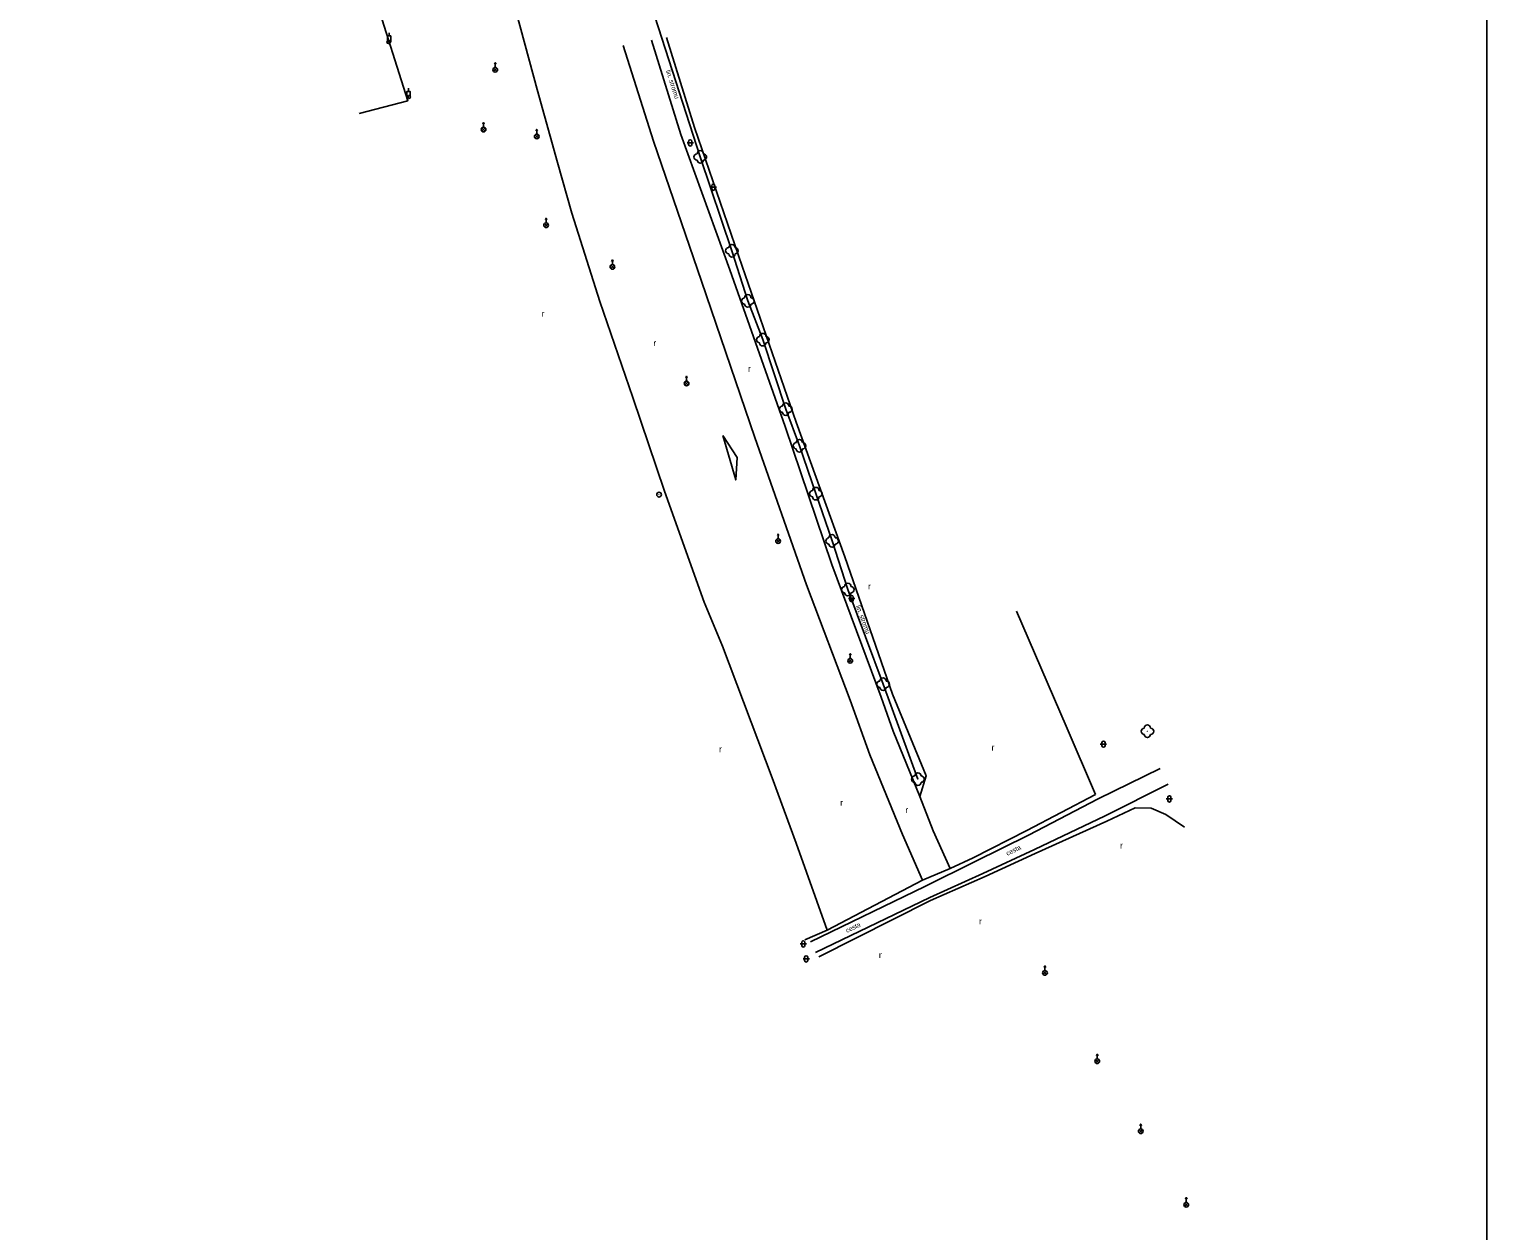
# Model space of a CAD drawing. Extents: x -582188 to -561562, y -1187250 to -1183500.
# Drawn here: x -575231.7 to -575000, y -1184245.2 to -1184054.2 of the extents above; entities that cross this region are included whole.
import ezdxf

# ---------------------------------------------------------------- set-up
doc = ezdxf.new("R2010")
doc.units = 0
for name, color, linetype in [('MAP_ZN_BP', 7, 'Continuous'), ('POMOC_POPIS', 7, 'Continuous'), ('ROZHRANÍ_PLOCH', 7, 'Continuous'), ('RÁMY_ML', 7, 'Continuous'), ('ZELEŇ', 7, 'Continuous'), ('ZN_BP', 7, 'Continuous'), ('ZN_DOPLŇKOVÉ', 7, 'Continuous'), ('ZN_KULTUR', 7, 'Continuous')]:
    doc.layers.add(name, color=color, linetype=linetype)

msp = doc.modelspace()

# ---------------------------------------------------------------- linework, layer by layer
at = {"layer": 'MAP_ZN_BP'}
for radius in [0.375, 0.0005]:
    msp.add_circle((-575131.55, -1184128.201), radius, dxfattribs=at)
at = {"layer": 'ROZHRANÍ_PLOCH'}
for points in [[(-575081.29, -1184186.5), (-575072.84, -1184182.35), (-575061.75, -1184176.54), (-575051.91, -1184171.73)], [(-575071.91, -1184184.6), (-575060.65, -1184179.26), (-575050.64, -1184174.21)], [(-575081.29, -1184186.5), (-575089.3, -1184190.46), (-575107.48, -1184199.28)], [(-575071.91, -1184184.6), (-575080.09, -1184188.4), (-575088.51, -1184192.26), (-575106.68, -1184200.98)]]:
    msp.add_lwpolyline(points, dxfattribs=at)
at = {"layer": 'RÁMY_ML'}
msp.add_lwpolyline([(-575312.5, -1184250), (-575000, -1184250), (-575000, -1184000)], dxfattribs=at)
at = {"layer": 'ZELEŇ'}
msp.add_line((-575073.09, -1184181.61), (-575062.19, -1184175.86), dxfattribs=at)
for points in [[(-575179.21, -1184067.59), (-575171.49, -1184065.59), (-575176.62, -1184049.33), (-575179.23, -1184040.68), (-575185.64, -1184019.24), (-575189.1, -1184003.71), (-575190.37, -1183993.69), (-575191.86, -1183981.98), (-575193.32, -1183970.15), (-575194.4, -1183962.03), (-575192.31, -1183959.76)], [(-575104.83, -1184197.43), (-575109.77, -1184183.61), (-575113.58, -1184173.2), (-575121.49, -1184152.31), (-575124.38, -1184145.28), (-575130.7, -1184127.65), (-575135.73, -1184112.74), (-575140.94, -1184097.5), (-575145.39, -1184083.44), (-575147.68, -1184075.42), (-575150.9, -1184063.82), (-575153.51, -1184054.2), (-575156.03, -1184045), (-575158.66, -1184034.48), (-575160.37, -1184027)], [(-575090.41, -1184173.42), (-575095.95, -1184158.33), (-575101.56, -1184143.29), (-575104.06, -1184135.55), (-575106.64, -1184128.04), (-575109.25, -1184120.43), (-575111.42, -1184114.61), (-575115.07, -1184103.56), (-575117.45, -1184097.41), (-575119.97, -1184089.43), (-575125, -1184074.52), (-575132.23, -1184052.22)], [(-575089.69, -1184189.5), (-575092.87, -1184182.2), (-575098.08, -1184169.56), (-575101.17, -1184160.88), (-575108.1, -1184142.54), (-575116.35, -1184119.12), (-575124.82, -1184094.24), (-575132.43, -1184072.01), (-575137.25, -1184056.81)], [(-575085.28, -1184187.62), (-575087.97, -1184181.62), (-575090.13, -1184176.19), (-575094.34, -1184165.77), (-575096.23, -1184160.37), (-575104.08, -1184139.29), (-575111.53, -1184117.36), (-575120.29, -1184092.46), (-575128.08, -1184070.93), (-575132.73, -1184055.97)], [(-575090.13, -1184176.19), (-575089.13, -1184172.9), (-575094.46, -1184159.89), (-575102.02, -1184138.09), (-575109.77, -1184116.67), (-575118.35, -1184091.9), (-575125.92, -1184069.83), (-575130.39, -1184055.53)], [(-575121.44, -1184118.78), (-575119.14, -1184122.27), (-575119.36, -1184125.86), (-575121.44, -1184118.78)], [(-575062.19, -1184175.86), (-575066.83, -1184165), (-575074.74, -1184146.72)], [(-575079.73, -1184188.92), (-575071.8, -1184185.22), (-575060.37, -1184180.12), (-575055.89, -1184177.97), (-575053.34, -1184178.03), (-575051, -1184179.05), (-575048.04, -1184181.08)], [(-575073.09, -1184181.61), (-575081.66, -1184185.94), (-575085.28, -1184187.62), (-575089.69, -1184189.5), (-575104.83, -1184197.43), (-575108.41, -1184198.96)], [(-575079.73, -1184188.92), (-575088.41, -1184192.7), (-575106.16, -1184201.67)]]:
    msp.add_lwpolyline(points, dxfattribs=at)
for centre in [(-575125, -1184074.52), (-575119.97, -1184089.43), (-575117.45, -1184097.41), (-575115.07, -1184103.56), (-575111.42, -1184114.61), (-575109.25, -1184120.43), (-575106.64, -1184128.04), (-575104.06, -1184135.55), (-575101.56, -1184143.29), (-575095.95, -1184158.33), (-575053.94, -1184165.81), (-575090.41, -1184173.42)]:
    msp.add_circle(centre, 0.0005, dxfattribs=at)
for centre, start, end in [((-575125.5, -1184074.52), 89.99999, 269.99999), ((-575125, -1184074.02), 0, 179.99999), ((-575125, -1184075.02), 179.99999, 359.99999), ((-575124.5, -1184074.52), 270, 89.99999), ((-575120.47, -1184089.43), 89.99999, 269.99999), ((-575119.97, -1184088.93), 0, 179.99999), ((-575119.47, -1184089.43), 270, 89.99999), ((-575119.97, -1184089.93), 179.99999, 359.99999), ((-575117.45, -1184096.91), 0, 179.99999), ((-575117.95, -1184097.41), 89.99999, 269.99999), ((-575117.45, -1184097.91), 179.99999, 359.99999), ((-575116.95, -1184097.41), 270, 89.99999), ((-575115.57, -1184103.56), 89.99999, 269.99999), ((-575115.07, -1184103.06), 0, 179.99999), ((-575114.57, -1184103.56), 270, 89.99999), ((-575115.07, -1184104.06), 179.99999, 359.99999), ((-575111.92, -1184114.61), 89.99999, 269.99999), ((-575111.42, -1184114.11), 0, 179.99999), ((-575110.92, -1184114.61), 270, 89.99999), ((-575111.42, -1184115.11), 179.99999, 359.99999), ((-575109.25, -1184119.93), 0, 179.99999), ((-575109.75, -1184120.43), 89.99999, 269.99999), ((-575109.25, -1184120.93), 179.99999, 359.99999), ((-575108.75, -1184120.43), 270, 89.99999), ((-575107.14, -1184128.04), 89.99999, 269.99999), ((-575106.64, -1184127.54), 0, 179.99999), ((-575106.64, -1184128.54), 179.99999, 359.99999), ((-575106.14, -1184128.04), 270, 89.99999), ((-575104.56, -1184135.55), 89.99999, 269.99999), ((-575104.06, -1184135.05), 0, 179.99999), ((-575103.56, -1184135.55), 270, 89.99999), ((-575104.06, -1184136.05), 179.99999, 359.99999), ((-575102.06, -1184143.29), 89.99999, 269.99999), ((-575101.56, -1184142.79), 0, 179.99999), ((-575101.06, -1184143.29), 270, 89.99999), ((-575101.56, -1184143.79), 179.99999, 359.99999), ((-575096.45, -1184158.33), 89.99999, 269.99999), ((-575095.95, -1184157.83), 0, 179.99999), ((-575095.95, -1184158.83), 179.99999, 359.99999), ((-575095.45, -1184158.33), 270, 89.99999), ((-575054.44, -1184165.81), 89.99999, 269.99999), ((-575053.94, -1184165.31), 0, 179.99999), ((-575053.44, -1184165.81), 270, 89.99999), ((-575053.94, -1184166.31), 179.99999, 359.99999), ((-575090.41, -1184172.92), 0, 179.99999), ((-575090.91, -1184173.42), 89.99999, 269.99999), ((-575090.41, -1184173.92), 179.99999, 359.99999), ((-575089.91, -1184173.42), 270, 89.99999)]:
    msp.add_arc(centre, 0.5, start, end, dxfattribs=at)
at = {"layer": 'ZN_BP'}
for p, q in [((-575157.855, -1184060.934), (-575157.326, -1184060.406)), ((-575157.326, -1184060.938), (-575157.855, -1184060.406)), ((-575157.59, -1184060.295), (-575157.59, -1184059.545)), ((-575159.715, -1184070.434), (-575159.186, -1184069.906)), ((-575159.186, -1184070.438), (-575159.715, -1184069.906)), ((-575159.45, -1184069.795), (-575159.45, -1184069.045)), ((-575150.99, -1184070.885), (-575150.99, -1184070.135)), ((-575151.255, -1184071.524), (-575150.726, -1184070.996)), ((-575150.726, -1184071.528), (-575151.255, -1184070.996)), ((-575149.5, -1184085.005), (-575149.5, -1184084.255)), ((-575149.765, -1184085.644), (-575149.236, -1184085.116)), ((-575149.236, -1184085.648), (-575149.765, -1184085.116)), ((-575139.225, -1184092.264), (-575138.696, -1184091.736)), ((-575138.696, -1184092.268), (-575139.225, -1184091.736)), ((-575138.96, -1184091.625), (-575138.96, -1184090.875)), ((-575127.455, -1184110.774), (-575126.926, -1184110.246)), ((-575126.926, -1184110.778), (-575127.455, -1184110.246)), ((-575127.19, -1184110.135), (-575127.19, -1184109.385)), ((-575112.895, -1184135.844), (-575112.366, -1184135.316)), ((-575112.366, -1184135.848), (-575112.895, -1184135.316)), ((-575112.63, -1184135.205), (-575112.63, -1184134.455)), ((-575101.435, -1184154.874), (-575100.906, -1184154.346)), ((-575100.906, -1184154.878), (-575101.435, -1184154.346)), ((-575101.17, -1184154.235), (-575101.17, -1184153.485)), ((-575070.485, -1184204.494), (-575069.956, -1184203.966)), ((-575069.956, -1184204.498), (-575070.485, -1184203.966)), ((-575070.22, -1184203.855), (-575070.22, -1184203.105)), ((-575062.185, -1184218.534), (-575061.656, -1184218.006)), ((-575061.656, -1184218.538), (-575062.185, -1184218.006)), ((-575061.92, -1184217.895), (-575061.92, -1184217.145)), ((-575055.01, -1184229.005), (-575055.01, -1184228.255)), ((-575055.275, -1184229.644), (-575054.746, -1184229.116)), ((-575054.746, -1184229.648), (-575055.275, -1184229.116)), ((-575047.77, -1184240.695), (-575047.77, -1184239.945)), ((-575048.035, -1184241.334), (-575047.506, -1184240.806)), ((-575047.506, -1184241.338), (-575048.035, -1184240.806))]:
    msp.add_line(p, q, dxfattribs=at)
for points in [[(-575157.715, -1184059.795), (-575157.59, -1184059.545), (-575157.465, -1184059.795)], [(-575159.575, -1184069.295), (-575159.45, -1184069.045), (-575159.325, -1184069.295)], [(-575151.115, -1184070.385), (-575150.99, -1184070.135), (-575150.865, -1184070.385)], [(-575149.625, -1184084.505), (-575149.5, -1184084.255), (-575149.375, -1184084.505)], [(-575139.085, -1184091.125), (-575138.96, -1184090.875), (-575138.835, -1184091.125)], [(-575127.315, -1184109.635), (-575127.19, -1184109.385), (-575127.065, -1184109.635)], [(-575112.755, -1184134.705), (-575112.63, -1184134.455), (-575112.505, -1184134.705)], [(-575101.295, -1184153.735), (-575101.17, -1184153.485), (-575101.045, -1184153.735)], [(-575070.345, -1184203.355), (-575070.22, -1184203.105), (-575070.095, -1184203.355)], [(-575062.045, -1184217.395), (-575061.92, -1184217.145), (-575061.795, -1184217.395)], [(-575055.135, -1184228.505), (-575055.01, -1184228.255), (-575054.885, -1184228.505)], [(-575047.895, -1184240.195), (-575047.77, -1184239.945), (-575047.645, -1184240.195)]]:
    msp.add_lwpolyline(points, dxfattribs=at)
for centre, radius in [((-575174.54, -1184056.25), 0.25), ((-575174.54, -1184056.25), 0.0005), ((-575157.59, -1184060.67), 0.375), ((-575171.32, -1184064.99), 0.25), ((-575171.32, -1184064.99), 0.0005), ((-575159.45, -1184070.17), 0.375), ((-575150.99, -1184071.26), 0.375), ((-575149.5, -1184085.38), 0.375), ((-575138.96, -1184092), 0.375), ((-575127.19, -1184110.51), 0.375), ((-575112.63, -1184135.58), 0.375), ((-575101.17, -1184154.61), 0.375), ((-575070.22, -1184204.23), 0.375), ((-575061.92, -1184218.27), 0.375), ((-575055.01, -1184229.38), 0.375), ((-575047.77, -1184241.07), 0.375)]:
    msp.add_circle(centre, radius, dxfattribs=at)
at = {"layer": 'ZN_DOPLŇKOVÉ'}
for p, q in [((-575174.44, -1184055.29), (-575174.44, -1184054.79)), ((-575171.36, -1184064.09), (-575171.36, -1184063.59))]:
    msp.add_line(p, q, dxfattribs=at)
for points in [[(-575174.69, -1184056.29), (-575174.69, -1184055.29), (-575174.19, -1184055.29), (-575174.19, -1184056.29)], [(-575171.61, -1184065.09), (-575171.61, -1184064.09), (-575171.11, -1184064.09), (-575171.11, -1184065.09)]]:
    msp.add_lwpolyline(points, dxfattribs=at)
at = {"layer": 'ZN_KULTUR'}
for p, q in [((-575127.1, -1184072.29), (-575126.1, -1184072.29)), ((-575126.85, -1184072.54), (-575126.85, -1184072.04)), ((-575126.35, -1184072.54), (-575126.35, -1184072.04)), ((-575123.43, -1184079.34), (-575122.43, -1184079.34)), ((-575123.18, -1184079.59), (-575123.18, -1184079.09)), ((-575122.68, -1184079.59), (-575122.68, -1184079.09)), ((-575101.46, -1184144.73), (-575100.46, -1184144.73)), ((-575101.21, -1184144.98), (-575101.21, -1184144.48)), ((-575100.71, -1184144.98), (-575100.71, -1184144.48)), ((-575061.43, -1184167.86), (-575060.43, -1184167.86)), ((-575061.18, -1184168.11), (-575061.18, -1184167.61)), ((-575060.68, -1184168.11), (-575060.68, -1184167.61)), ((-575050.95, -1184176.56), (-575049.95, -1184176.56)), ((-575050.7, -1184176.81), (-575050.7, -1184176.31)), ((-575050.2, -1184176.81), (-575050.2, -1184176.31)), ((-575109.13, -1184199.62), (-575108.13, -1184199.62)), ((-575108.88, -1184199.87), (-575108.88, -1184199.37)), ((-575108.38, -1184199.87), (-575108.38, -1184199.37)), ((-575108.67, -1184201.99), (-575107.67, -1184201.99)), ((-575108.42, -1184202.24), (-575108.42, -1184201.74)), ((-575107.92, -1184202.24), (-575107.92, -1184201.74))]:
    msp.add_line(p, q, dxfattribs=at)
for centre, start, end in [((-575126.6, -1184072.04), 0, 179.99999), ((-575126.6, -1184072.54), 179.99999, 359.99999), ((-575122.93, -1184079.09), 0, 179.99999), ((-575122.93, -1184079.59), 179.99999, 359.99999), ((-575100.96, -1184144.48), 0, 179.99999), ((-575100.96, -1184144.98), 179.99999, 359.99999), ((-575060.93, -1184167.61), 0, 179.99999), ((-575060.93, -1184168.11), 179.99999, 359.99999), ((-575050.45, -1184176.31), 0, 179.99999), ((-575050.45, -1184176.81), 179.99999, 359.99999), ((-575108.63, -1184199.37), 0, 179.99999), ((-575108.63, -1184199.87), 179.99999, 359.99999), ((-575108.17, -1184201.74), 0, 179.99999), ((-575108.17, -1184202.24), 179.99999, 359.99999)]:
    msp.add_arc(centre, 0.25, start, end, dxfattribs=at)

# ---------------------------------------------------------------- texts
at = {"layer": 'POMOC_POPIS'}
for p in [(-575076.19, -1184185.61), (-575101.68, -1184197.87)]:
    msp.add_text('cesta', height=0.75, rotation=25.63691, dxfattribs=at).set_placement(p)
at = {"layer": 'ZELEŇ'}
for rotation, p in [(287.96348, (-575130.49, -1184060.82)), (290.45578, (-575100.3, -1184145.94))]:
    msp.add_text('lin. stromu', height=0.75, rotation=rotation, dxfattribs=at).set_placement(p)
at = {"layer": 'ZN_KULTUR'}
for p in [(-575150.218, -1184099.932), (-575132.438, -1184104.582), (-575117.418, -1184108.692), (-575098.348, -1184143.262), (-575078.718, -1184168.882), (-575122.018, -1184169.152), (-575102.758, -1184177.652), (-575092.398, -1184178.812), (-575058.278, -1184184.462), (-575080.718, -1184196.522), (-575096.618, -1184201.862)]:
    msp.add_text('r', height=1, dxfattribs=at).set_placement(p)

doc.saveas('drawing.dxf')
